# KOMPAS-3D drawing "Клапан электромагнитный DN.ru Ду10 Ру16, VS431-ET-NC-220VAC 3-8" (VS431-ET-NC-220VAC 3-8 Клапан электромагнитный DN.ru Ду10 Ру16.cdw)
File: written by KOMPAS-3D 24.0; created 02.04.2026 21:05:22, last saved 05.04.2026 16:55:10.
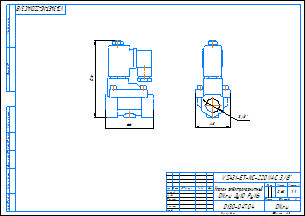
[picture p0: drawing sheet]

Document properties: c3d_UniqueCompID: ef56311e-7521-43dc-8291-0e6108b3d81d; Обозначение: VS400-ET-NC-220VAC 3-8; Наименование: Клапан электромагнитный DN.ru Ду10 Ру16; Автор: artio; Класс точности: c; Знак неуказанной шероховатости: Шероховатость не задана; Рассекать на разрезах: Да; Автор: artio; Форматы листов документа: A3; Полное имя файла: VS431-ET-NC-220VAC 3-8 Клапан электромагнитный DN.ru Ду10 Ру16.m3d; Масса: 0.62; Наименование: Клапан электромагнитный DN.ru Ду10 Ру16; Количество листов документа: 1; Примечание: D130-04704

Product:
- Body: Тело 1  | qty 1
    Масса: 1.030062
- Part/product: Клапан электромагнитный DN.ru Ду10 Ру16  | designation VS431-ET-NC-220VAC 3-8
    Масса: 0.62
    Раздел спецификации: Прочие изделия
    Примечание: D130-04704
    additional columns: ef56311e-7521-43dc-8291-0e6108b3d81d; VS400-ET-NC-220VAC 3-8; artio; c; Шероховатость не задана; Да

Views: Вид 1, Спереди, Проекционный вид 2
Referenced files in C:\Users\artio\OneDrive\Рабочий стол\Клапан электромагнитный DN.ru VS4x-xT-NC-x\DN10\: VS400-ET-NC-220VAC 3-8 Клапан электромагнитный DN.ru Ду10 Ру16.m3d
Referenced files in C:\Users\artio\OneDrive\Рабочий стол\Клапан электромагнитный DN.ru\VS431\VS431-ET-NC\VS431-ET-NC-220VAC\Ду10\: VS431-ET-NC-220VAC 3-8 Клапан электромагнитный DN.ru Ду10 Ру16.m3d, VS431-ET-NC-220VAC 3-8 Клапан электромагнитный DN.ru Ду10 Ру16.cdw
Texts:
  VS431-ET-NC-220VAC 3-8
  Линейный размер
  Клапан электромагнитный
  DN.ru Ду10 Ру16
  VS431-ET-NC-220VAC 3/8"
  VS431-ET-NC-220VAC 3/8"-
  Клапан электромагнитный DN.ru Ду10 Ру16
  VS431-ET-NC-220VAC 3-8 Клапан электромагнитный DN.ru Ду10 Ру16
Dimensions and other numbers on the sheet: 0; 3; 2; 4; 48; 3/8"; 66; 106; 1:1; 1; 0,62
